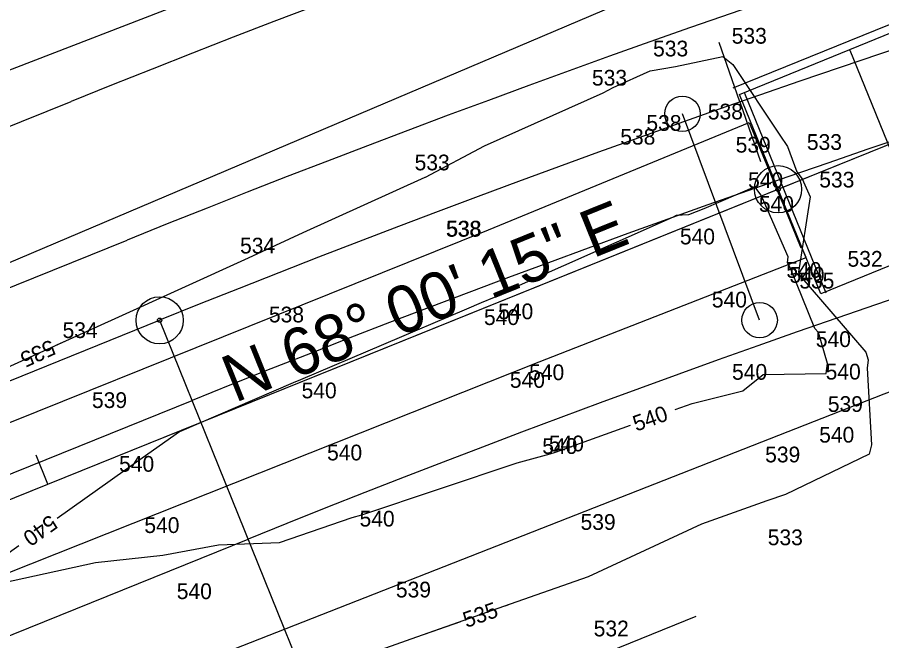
# Model space of a CAD drawing. Extents: x 1787461 to 1970323, y 938412 to 1118748.
# Drawn here: x 1967600.1 to 1967710, y 1117774.7 to 1117853.9 of the extents above; entities that cross this region are included whole.
import ezdxf

# ---------------------------------------------------------------- set-up
doc = ezdxf.new("R2010")
doc.units = 0
for name, color, linetype in [('Default', 7, 'Continuous'), ('HHA ADDITIONAL XSs', 7, 'Continuous'), ('Level 19', 7, 'Continuous'), ('RD_EX_Bridge', 7, 'Continuous'), ('RD_EX_DV_Prop', 7, 'Continuous'), ('RD_EX_Fence_Other', 7, 'Continuous'), ('RD_EX_Misc', 7, 'Continuous'), ('RD_EX_Road', 7, 'Continuous'), ('RD_EX_VEG', 7, 'Continuous'), ('RD_HC_CL', 7, 'Continuous'), ('RD_HC_CL_Rel', 7, 'Continuous'), ('RD_HC_Data', 7, 'Continuous'), ('RD_HC_Data_Rel', 7, 'Continuous'), ('RD_HC_Data_Tic', 7, 'Continuous'), ('RD_HC_Data_Tic_Rel', 7, 'Continuous'), ('RD_PD_Final_TrvlWay', 7, 'Continuous'), ('RD_SMD_Locator', 7, 'Continuous')]:
    doc.layers.add(name, color=color, linetype=linetype)

msp = doc.modelspace()

# ---------------------------------------------------------------- linework, layer by layer
at = {"layer": 'Default'}
for points in [[(1967588.63, 1117804.76), (1967606.77, 1117813), (1967612.54, 1117815.64), (1967629.5, 1117823.35), (1967636.45, 1117826.54), (1967651.98, 1117833.6), (1967652, 1117833.61), (1967659.52, 1117837.57), (1967674.59, 1117844.3), (1967675.89, 1117844.98), (1967680.6, 1117847.09), (1967683.81, 1117847.65), (1967689.8, 1117848.93), (1967691.11, 1117847.9), (1967697.07, 1117838.93), (1967698.06, 1117837.48), (1967699.22, 1117834.26), (1967699.9, 1117833.4), (1967700.92, 1117831.08), (1967699.46, 1117821.5), (1967699.48, 1117821.47), (1967699.63, 1117821.09), (1967708.02, 1117811.34), (1967708.3, 1117810.39), (1967708.17, 1117809.3), (1967708.72, 1117799.55), (1967708.42, 1117798.39), (1967697.77, 1117793.27), (1967695.42, 1117792.44), (1967687.12, 1117789.5), (1967672.71, 1117782.8), (1967662.77, 1117779.31), (1967650.85, 1117775.1), (1967634.97, 1117769.49)], [(1967605.16, 1117812.27), (1967606.77, 1117813), (1967612.54, 1117815.64), (1967629.5, 1117823.35), (1967636.45, 1117826.54), (1967651.98, 1117833.6), (1967652, 1117833.61), (1967659.52, 1117837.57), (1967674.59, 1117844.3), (1967675.89, 1117844.98), (1967680.6, 1117847.09), (1967683.81, 1117847.65), (1967689.8, 1117848.93), (1967691.11, 1117847.9), (1967697.07, 1117838.93), (1967698.06, 1117837.48), (1967699.22, 1117834.26), (1967699.9, 1117833.4), (1967700.92, 1117831.08), (1967699.46, 1117821.5), (1967699.48, 1117821.47), (1967699.63, 1117821.09), (1967708.02, 1117811.34), (1967708.3, 1117810.39), (1967708.17, 1117809.3), (1967708.72, 1117799.55), (1967708.42, 1117798.39), (1967697.77, 1117793.27), (1967695.42, 1117792.44), (1967687.12, 1117789.5), (1967672.71, 1117782.8), (1967662.77, 1117779.31), (1967662.13, 1117779.08)], [(1967605.16, 1117812.27), (1967606.77, 1117813), (1967612.54, 1117815.64), (1967629.5, 1117823.35), (1967636.45, 1117826.54), (1967651.98, 1117833.6), (1967652, 1117833.61), (1967659.52, 1117837.57), (1967674.59, 1117844.3), (1967675.89, 1117844.98), (1967680.6, 1117847.09), (1967683.81, 1117847.65), (1967689.8, 1117848.93), (1967691.11, 1117847.9), (1967697.07, 1117838.93), (1967698.06, 1117837.48), (1967699.22, 1117834.26), (1967699.9, 1117833.4), (1967700.92, 1117831.08), (1967699.46, 1117821.5), (1967699.48, 1117821.47), (1967699.63, 1117821.09), (1967708.02, 1117811.34), (1967708.3, 1117810.39), (1967708.17, 1117809.3), (1967708.72, 1117799.55), (1967708.42, 1117798.39), (1967697.77, 1117793.27), (1967695.42, 1117792.44), (1967687.12, 1117789.5), (1967672.71, 1117782.8), (1967662.77, 1117779.31), (1967662.13, 1117779.08)], [(1967605.16, 1117812.27), (1967606.77, 1117813), (1967612.54, 1117815.64), (1967629.5, 1117823.35), (1967636.45, 1117826.54), (1967651.98, 1117833.6), (1967652, 1117833.61), (1967659.52, 1117837.57), (1967674.59, 1117844.3), (1967675.89, 1117844.98), (1967680.6, 1117847.09), (1967683.81, 1117847.65), (1967689.8, 1117848.93), (1967691.11, 1117847.9), (1967697.07, 1117838.93), (1967698.06, 1117837.48), (1967699.22, 1117834.26), (1967699.9, 1117833.4), (1967700.92, 1117831.08), (1967699.46, 1117821.5), (1967699.48, 1117821.47), (1967699.63, 1117821.09), (1967708.02, 1117811.34), (1967708.3, 1117810.39), (1967708.17, 1117809.3), (1967708.72, 1117799.55), (1967708.42, 1117798.39), (1967697.77, 1117793.27), (1967695.42, 1117792.44), (1967687.12, 1117789.5), (1967672.71, 1117782.8), (1967662.77, 1117779.31), (1967662.13, 1117779.08)], [(1967605.16, 1117812.27), (1967606.77, 1117813), (1967612.54, 1117815.64), (1967629.5, 1117823.35), (1967636.45, 1117826.54), (1967651.98, 1117833.6), (1967652, 1117833.61), (1967659.52, 1117837.57), (1967674.59, 1117844.3), (1967675.89, 1117844.98), (1967680.6, 1117847.09), (1967683.81, 1117847.65), (1967689.8, 1117848.93), (1967691.11, 1117847.9), (1967697.07, 1117838.93), (1967698.06, 1117837.48), (1967699.22, 1117834.26), (1967699.9, 1117833.4), (1967700.92, 1117831.08), (1967699.46, 1117821.5), (1967699.48, 1117821.47), (1967699.63, 1117821.09), (1967708.02, 1117811.34), (1967708.3, 1117810.39), (1967708.17, 1117809.3), (1967708.72, 1117799.55), (1967708.42, 1117798.39), (1967697.77, 1117793.27), (1967695.42, 1117792.44), (1967687.12, 1117789.5), (1967672.71, 1117782.8), (1967662.77, 1117779.31), (1967662.13, 1117779.08)], [(1967605.16, 1117812.27), (1967606.77, 1117813), (1967612.54, 1117815.64), (1967629.5, 1117823.35), (1967636.45, 1117826.54), (1967651.98, 1117833.6), (1967652, 1117833.61), (1967659.52, 1117837.57), (1967674.59, 1117844.3), (1967675.89, 1117844.98), (1967680.6, 1117847.09), (1967683.81, 1117847.65), (1967689.8, 1117848.93), (1967691.11, 1117847.9), (1967697.07, 1117838.93), (1967698.06, 1117837.48), (1967699.22, 1117834.26), (1967699.9, 1117833.4), (1967700.92, 1117831.08), (1967699.46, 1117821.5), (1967699.48, 1117821.47), (1967699.63, 1117821.09), (1967708.02, 1117811.34), (1967708.3, 1117810.39), (1967708.17, 1117809.3), (1967708.72, 1117799.55), (1967708.42, 1117798.39), (1967697.77, 1117793.27), (1967695.42, 1117792.44), (1967687.12, 1117789.5), (1967672.71, 1117782.8), (1967662.77, 1117779.31), (1967662.13, 1117779.08)], [(1967605.16, 1117812.27), (1967606.77, 1117813), (1967612.54, 1117815.64), (1967629.5, 1117823.35), (1967636.45, 1117826.54), (1967651.98, 1117833.6), (1967652, 1117833.61), (1967659.52, 1117837.57), (1967674.59, 1117844.3), (1967675.89, 1117844.98), (1967680.6, 1117847.09), (1967683.81, 1117847.65), (1967689.8, 1117848.93), (1967691.11, 1117847.9), (1967697.07, 1117838.93), (1967698.06, 1117837.48), (1967699.22, 1117834.26), (1967699.9, 1117833.4), (1967700.92, 1117831.08), (1967699.46, 1117821.5), (1967699.48, 1117821.47), (1967699.63, 1117821.09), (1967708.02, 1117811.34), (1967708.3, 1117810.39), (1967708.17, 1117809.3), (1967708.72, 1117799.55), (1967708.42, 1117798.39), (1967697.77, 1117793.27), (1967695.42, 1117792.44), (1967687.12, 1117789.5), (1967672.71, 1117782.8), (1967662.77, 1117779.31), (1967662.13, 1117779.08)], [(1967694.7, 1117831.31), (1967693.87, 1117832.37), (1967687.42, 1117829.58), (1967685.44, 1117828.82), (1967683.88, 1117828.7), (1967683.5, 1117828.5), (1967662.39, 1117819.16), (1967660.76, 1117818.3), (1967659.11, 1117817.6), (1967659.11, 1117817.6), (1967657.23, 1117816.83), (1967636.11, 1117807.81), (1967635.18, 1117807.43), (1967620.73, 1117801.23), (1967613.81, 1117796.33), (1967605.18, 1117790.19)], [(1967694.7, 1117831.31), (1967693.87, 1117832.37), (1967687.42, 1117829.58), (1967685.44, 1117828.82), (1967683.88, 1117828.7), (1967683.5, 1117828.5), (1967662.39, 1117819.16), (1967660.76, 1117818.3), (1967659.11, 1117817.6), (1967659.11, 1117817.6), (1967657.23, 1117816.83), (1967636.11, 1117807.81), (1967635.18, 1117807.43), (1967620.73, 1117801.23), (1967613.81, 1117796.33), (1967605.18, 1117790.19)], [(1967694.7, 1117831.31), (1967693.87, 1117832.37), (1967687.42, 1117829.58), (1967685.44, 1117828.82), (1967683.88, 1117828.7), (1967683.5, 1117828.5), (1967662.39, 1117819.16), (1967660.76, 1117818.3), (1967659.11, 1117817.6), (1967659.11, 1117817.6), (1967657.23, 1117816.83), (1967636.11, 1117807.81), (1967635.18, 1117807.43), (1967620.73, 1117801.23), (1967613.81, 1117796.33), (1967605.18, 1117790.19)], [(1967694.7, 1117831.31), (1967693.87, 1117832.37), (1967687.42, 1117829.58), (1967685.44, 1117828.82), (1967683.88, 1117828.7), (1967683.5, 1117828.5), (1967662.39, 1117819.16), (1967660.76, 1117818.3), (1967659.11, 1117817.6), (1967659.11, 1117817.6), (1967657.23, 1117816.83), (1967636.11, 1117807.81), (1967635.18, 1117807.43), (1967620.73, 1117801.23), (1967613.81, 1117796.33), (1967605.18, 1117790.19)], [(1967694.7, 1117831.31), (1967693.87, 1117832.37), (1967687.42, 1117829.58), (1967685.44, 1117828.82), (1967683.88, 1117828.7), (1967683.5, 1117828.5), (1967662.39, 1117819.16), (1967660.76, 1117818.3), (1967659.11, 1117817.6), (1967659.11, 1117817.6), (1967657.23, 1117816.83), (1967636.11, 1117807.81), (1967635.18, 1117807.43), (1967620.73, 1117801.23), (1967613.81, 1117796.33), (1967605.18, 1117790.19)], [(1967694.7, 1117831.31), (1967693.87, 1117832.37), (1967687.42, 1117829.58), (1967685.44, 1117828.82), (1967683.88, 1117828.7), (1967683.5, 1117828.5), (1967662.39, 1117819.16), (1967660.76, 1117818.3), (1967659.11, 1117817.6), (1967659.11, 1117817.6), (1967657.23, 1117816.83), (1967636.11, 1117807.81), (1967635.18, 1117807.43), (1967620.73, 1117801.23), (1967613.81, 1117796.33), (1967605.18, 1117790.19)], [(1967694.7, 1117831.31), (1967693.87, 1117832.37), (1967687.42, 1117829.58), (1967685.44, 1117828.82), (1967683.88, 1117828.7), (1967683.5, 1117828.5), (1967662.39, 1117819.16), (1967660.76, 1117818.3), (1967659.11, 1117817.6), (1967659.11, 1117817.6), (1967657.23, 1117816.83), (1967636.11, 1117807.81), (1967635.18, 1117807.43), (1967620.73, 1117801.23), (1967613.81, 1117796.33), (1967605.18, 1117790.19)], [(1967683.75, 1117804.06), (1967685.94, 1117804.84), (1967692.35, 1117806.45), (1967694.94, 1117808.51), (1967702.97, 1117808.62), (1967703.12, 1117809.89), (1967701.97, 1117813.86), (1967701.53, 1117814.37), (1967698.39, 1117822.11), (1967698.02, 1117822.7), (1967698.13, 1117823.46), (1967694.7, 1117831.31)], [(1967683.75, 1117804.06), (1967685.94, 1117804.84), (1967692.35, 1117806.45), (1967694.94, 1117808.51), (1967702.97, 1117808.62), (1967703.12, 1117809.89), (1967701.97, 1117813.86), (1967701.53, 1117814.37), (1967698.39, 1117822.11), (1967698.02, 1117822.7), (1967698.13, 1117823.46), (1967694.7, 1117831.31)], [(1967683.75, 1117804.06), (1967685.94, 1117804.84), (1967692.35, 1117806.45), (1967694.94, 1117808.51), (1967702.97, 1117808.62), (1967703.12, 1117809.89), (1967701.97, 1117813.86), (1967701.53, 1117814.37), (1967698.39, 1117822.11), (1967698.02, 1117822.7), (1967698.13, 1117823.46), (1967694.7, 1117831.31)], [(1967683.75, 1117804.06), (1967685.94, 1117804.84), (1967692.35, 1117806.45), (1967694.94, 1117808.51), (1967702.97, 1117808.62), (1967703.12, 1117809.89), (1967701.97, 1117813.86), (1967701.53, 1117814.37), (1967698.39, 1117822.11), (1967698.02, 1117822.7), (1967698.13, 1117823.46), (1967694.7, 1117831.31)], [(1967683.75, 1117804.06), (1967685.94, 1117804.84), (1967692.35, 1117806.45), (1967694.94, 1117808.51), (1967702.97, 1117808.62), (1967703.12, 1117809.89), (1967701.97, 1117813.86), (1967701.53, 1117814.37), (1967698.39, 1117822.11), (1967698.02, 1117822.7), (1967698.13, 1117823.46), (1967694.7, 1117831.31)], [(1967683.75, 1117804.06), (1967685.94, 1117804.84), (1967692.35, 1117806.45), (1967694.94, 1117808.51), (1967702.97, 1117808.62), (1967703.12, 1117809.89), (1967701.97, 1117813.86), (1967701.53, 1117814.37), (1967698.39, 1117822.11), (1967698.02, 1117822.7), (1967698.13, 1117823.46), (1967694.7, 1117831.31)], [(1967683.75, 1117804.06), (1967685.94, 1117804.84), (1967692.35, 1117806.45), (1967694.94, 1117808.51), (1967702.97, 1117808.62), (1967703.12, 1117809.89), (1967701.97, 1117813.86), (1967701.53, 1117814.37), (1967698.39, 1117822.11), (1967698.02, 1117822.7), (1967698.13, 1117823.46), (1967694.7, 1117831.31)], [(1967600.29, 1117786.71), (1967596.07, 1117783.71), (1967592.9, 1117781.45), (1967591.69, 1117780.59), (1967592.73, 1117780.85), (1967593.14, 1117780.91), (1967610.04, 1117784.61), (1967618.63, 1117785.54), (1967625.68, 1117786.84), (1967633.46, 1117787.15), (1967642.7, 1117790.31), (1967643.9, 1117790.65), (1967663.69, 1117797.3), (1967667.86, 1117798.43), (1967668.54, 1117798.65), (1967678.1, 1117802.05)], [(1967600.29, 1117786.71), (1967596.07, 1117783.71), (1967592.9, 1117781.45), (1967591.69, 1117780.59), (1967592.73, 1117780.85), (1967593.14, 1117780.91), (1967610.04, 1117784.61), (1967618.63, 1117785.54), (1967625.68, 1117786.84), (1967633.46, 1117787.15), (1967642.7, 1117790.31), (1967643.9, 1117790.65), (1967663.69, 1117797.3), (1967667.86, 1117798.43), (1967668.54, 1117798.65), (1967678.1, 1117802.05)], [(1967600.29, 1117786.71), (1967596.07, 1117783.71), (1967592.9, 1117781.45), (1967591.69, 1117780.59), (1967592.73, 1117780.85), (1967593.14, 1117780.91), (1967610.04, 1117784.61), (1967618.63, 1117785.54), (1967625.68, 1117786.84), (1967633.46, 1117787.15), (1967642.7, 1117790.31), (1967643.9, 1117790.65), (1967663.69, 1117797.3), (1967667.86, 1117798.43), (1967668.54, 1117798.65), (1967678.1, 1117802.05)], [(1967600.29, 1117786.71), (1967596.07, 1117783.71), (1967592.9, 1117781.45), (1967591.69, 1117780.59), (1967592.73, 1117780.85), (1967593.14, 1117780.91), (1967610.04, 1117784.61), (1967618.63, 1117785.54), (1967625.68, 1117786.84), (1967633.46, 1117787.15), (1967642.7, 1117790.31), (1967643.9, 1117790.65), (1967663.69, 1117797.3), (1967667.86, 1117798.43), (1967668.54, 1117798.65), (1967678.1, 1117802.05)], [(1967600.29, 1117786.71), (1967596.07, 1117783.71), (1967592.9, 1117781.45), (1967591.69, 1117780.59), (1967592.73, 1117780.85), (1967593.14, 1117780.91), (1967610.04, 1117784.61), (1967618.63, 1117785.54), (1967625.68, 1117786.84), (1967633.46, 1117787.15), (1967642.7, 1117790.31), (1967643.9, 1117790.65), (1967663.69, 1117797.3), (1967667.86, 1117798.43), (1967668.54, 1117798.65), (1967678.1, 1117802.05)], [(1967600.29, 1117786.71), (1967596.07, 1117783.71), (1967592.9, 1117781.45), (1967591.69, 1117780.59), (1967592.73, 1117780.85), (1967593.14, 1117780.91), (1967610.04, 1117784.61), (1967618.63, 1117785.54), (1967625.68, 1117786.84), (1967633.46, 1117787.15), (1967642.7, 1117790.31), (1967643.9, 1117790.65), (1967663.69, 1117797.3), (1967667.86, 1117798.43), (1967668.54, 1117798.65), (1967678.1, 1117802.05)], [(1967600.29, 1117786.71), (1967596.07, 1117783.71), (1967592.9, 1117781.45), (1967591.69, 1117780.59), (1967592.73, 1117780.85), (1967593.14, 1117780.91), (1967610.04, 1117784.61), (1967618.63, 1117785.54), (1967625.68, 1117786.84), (1967633.46, 1117787.15), (1967642.7, 1117790.31), (1967643.9, 1117790.65), (1967663.69, 1117797.3), (1967667.86, 1117798.43), (1967668.54, 1117798.65), (1967678.1, 1117802.05)], [(1967656.47, 1117777.08), (1967650.85, 1117775.1), (1967634.97, 1117769.49), (1967627.29, 1117766.79), (1967610.06, 1117760.7), (1967603.74, 1117758.49), (1967584.74, 1117751.76), (1967580.2, 1117750.17), (1967577.14, 1117748.82), (1967576.43, 1117748.53), (1967554.96, 1117739.06), (1967553.54, 1117738.47), (1967543.93, 1117734.19), (1967539.4, 1117728.42), (1967538.83, 1117723.7), (1967524.23, 1117678.01), (1967542.42, 1117671.22)], [(1967656.47, 1117777.08), (1967650.85, 1117775.1), (1967634.97, 1117769.49), (1967627.29, 1117766.79), (1967610.06, 1117760.7), (1967603.74, 1117758.49), (1967584.74, 1117751.76), (1967580.2, 1117750.17), (1967577.14, 1117748.82), (1967576.43, 1117748.53), (1967554.96, 1117739.06), (1967553.54, 1117738.47), (1967543.93, 1117734.19), (1967539.4, 1117728.42), (1967538.83, 1117723.7), (1967524.23, 1117678.01), (1967542.42, 1117671.22)], [(1967656.47, 1117777.08), (1967650.85, 1117775.1), (1967634.97, 1117769.49), (1967627.29, 1117766.79), (1967610.06, 1117760.7), (1967603.74, 1117758.49), (1967584.74, 1117751.76), (1967580.2, 1117750.17), (1967577.14, 1117748.82), (1967576.43, 1117748.53), (1967554.96, 1117739.06), (1967553.54, 1117738.47), (1967543.93, 1117734.19), (1967539.4, 1117728.42), (1967538.83, 1117723.7), (1967524.23, 1117678.01), (1967542.42, 1117671.22)], [(1967656.47, 1117777.08), (1967650.85, 1117775.1), (1967634.97, 1117769.49), (1967627.29, 1117766.79), (1967610.06, 1117760.7), (1967603.74, 1117758.49), (1967584.74, 1117751.76), (1967580.2, 1117750.17), (1967577.14, 1117748.82), (1967576.43, 1117748.53), (1967554.96, 1117739.06), (1967553.54, 1117738.47), (1967543.93, 1117734.19), (1967539.4, 1117728.42), (1967538.83, 1117723.7), (1967524.23, 1117678.01), (1967542.42, 1117671.22)], [(1967656.47, 1117777.08), (1967650.85, 1117775.1), (1967634.97, 1117769.49), (1967627.29, 1117766.79), (1967610.06, 1117760.7), (1967603.74, 1117758.49), (1967584.74, 1117751.76), (1967580.2, 1117750.17), (1967577.14, 1117748.82), (1967576.43, 1117748.53), (1967554.96, 1117739.06), (1967553.54, 1117738.47), (1967543.93, 1117734.19), (1967539.4, 1117728.42), (1967538.83, 1117723.7), (1967524.23, 1117678.01), (1967542.42, 1117671.22)], [(1967656.47, 1117777.08), (1967650.85, 1117775.1), (1967634.97, 1117769.49), (1967627.29, 1117766.79), (1967610.06, 1117760.7), (1967603.74, 1117758.49), (1967584.74, 1117751.76), (1967580.2, 1117750.17), (1967577.14, 1117748.82), (1967576.43, 1117748.53), (1967554.96, 1117739.06), (1967553.54, 1117738.47), (1967543.93, 1117734.19), (1967539.4, 1117728.42), (1967538.83, 1117723.7), (1967524.23, 1117678.01), (1967542.42, 1117671.22)]]:
    msp.add_lwpolyline(points, dxfattribs=at)
at = {"layer": 'HHA ADDITIONAL XSs'}
for p, q in [((1967355.97, 1117741.82), (1967606.98, 1117843.22)), ((1967378.44, 1117686.19), (1967629.45, 1117787.58))]:
    msp.add_line(p, q, dxfattribs=at)
msp.add_lwpolyline([(1969266.55, 1117963.61), (1967907.56, 1117966.55), (1967403.98, 1117771.66), (1967075.57, 1117641.84)], dxfattribs=at)
for radius in [1667.02, 1607.02]:
    msp.add_arc((1968231.34, 1116297.54), radius, 87.72663, 111.99584, dxfattribs=at)
at = {"layer": 'Level 19'}
msp.add_line((1967694.5, 1117815.42), (1967684.68, 1117841.64), dxfattribs=at)
for centre in [(1967684.68, 1117841.64), (1967694.5, 1117815.42)]:
    msp.add_circle(centre, 2.25, dxfattribs=at)
at = {"layer": 'RD_EX_Bridge'}
msp.add_lwpolyline([(1967691.93, 1117844.09), (1967872.42, 1117917.74), (1967882.76, 1117892.41), (1967702.27, 1117818.76), (1967691.93, 1117844.09)], dxfattribs=at)
at = {"layer": 'RD_EX_DV_Prop'}
for p, q in [((1967696.84, 1117832.06), (1967823.97, 1117883.41)), ((1966769.51, 1117457.48), (1967696.84, 1117832.06))]:
    msp.add_line(p, q, dxfattribs=at)
at = {"layer": 'RD_EX_Fence_Other'}
msp.add_lwpolyline([(1967531.32, 1117716.68), (1967581.91, 1117735.39), (1967686.43, 1117777.78)], dxfattribs=at)
at = {"layer": 'RD_EX_Misc'}
for p, q in [((1967691.12, 1117844.93), (1967873.24, 1117918.94)), ((1967705.98, 1117849.73), (1967716.27, 1117824.34)), ((1967692.59, 1117844.26), (1967702.91, 1117818.87))]:
    msp.add_line(p, q, dxfattribs=at)
at = {"layer": 'RD_EX_Road'}
for points in [[(1966768.28, 1117466.83), (1966868.93, 1117506.7), (1966969.96, 1117548.31), (1967069.86, 1117589.6), (1967171.37, 1117630.89), (1967269.56, 1117671.02), (1967319.89, 1117691.93), (1967370.29, 1117712.23), (1967469.03, 1117750.91), (1967565.44, 1117788.86), (1967660.02, 1117826.88), (1967693.17, 1117840.55), (1967696.66, 1117832.16)], [(1967338.81, 1117679.22), (1967378.03, 1117695.56), (1967474.86, 1117733.75), (1967572.69, 1117772.86), (1967666.47, 1117810.1), (1967700.41, 1117823.36), (1967696.66, 1117832.16)]]:
    msp.add_lwpolyline(points, dxfattribs=at)
at = {"layer": 'RD_EX_VEG'}
for points in [[(1967420.8, 1117819.08), (1967452.15, 1117758.28), (1967558.57, 1117805.53), (1967843.24, 1117926.43), (1967916.63, 1117956.61), (1968008.44, 1117968.2), (1968060.25, 1117967.44), (1968104.58, 1117972.69), (1968157.63, 1117966.15), (1968211.15, 1117963.44), (1968421.93, 1117955.99), (1968535.19, 1117951.62)], [(1967302.31, 1117610.37), (1967337.76, 1117649.58), (1967352.05, 1117663.92), (1967393.53, 1117676.59), (1967483.38, 1117717.02), (1967710.35, 1117806.03), (1967888.86, 1117873.57), (1967928.06, 1117882.04), (1967957.92, 1117887.35), (1967975.7, 1117893.86), (1968013.09, 1117903.71), (1968102.91, 1117899.22), (1968154.08, 1117904.84), (1968208.62, 1117905.24), (1968319.32, 1117902.87), (1968421.81, 1117901.58), (1968527.92, 1117886.31)]]:
    msp.add_lwpolyline(points, dxfattribs=at)
at = {"layer": 'RD_HC_CL'}
msp.add_line((1966769.51, 1117457.48), (1967848.24, 1117893.22), dxfattribs=at)
at = {"layer": 'RD_HC_CL_Rel'}
msp.add_line((1967367.21, 1117714.01), (1967618.21, 1117815.4), dxfattribs=at)
msp.add_arc((1968231.34, 1116297.54), 1637.02, 87.72663, 111.99584, dxfattribs=at)
at = {"layer": 'RD_HC_Data'}
for radius in [3, 0.282]:
    msp.add_circle((1967696.84, 1117832.06), radius, dxfattribs=at)
at = {"layer": 'RD_HC_Data_Rel'}
msp.add_line((1967618.21, 1117815.4), (1967674.03, 1117677.23), dxfattribs=at)
for radius in [3, 0.282]:
    msp.add_circle((1967618.21, 1117815.4), radius, dxfattribs=at)
at = {"layer": 'RD_HC_Data_Tic'}
for p, q in [((1967696.72, 1117832.01), (1967693.73, 1117839.43)), ((1967696.72, 1117832.01), (1967699.72, 1117824.6)), ((1967604, 1117794.56), (1967602.5, 1117798.27))]:
    msp.add_line(p, q, dxfattribs=at)
at = {"layer": 'RD_HC_Data_Tic_Rel'}
for q in [(1967689.34, 1117850.7), (1967694.61, 1117835.6)]:
    msp.add_line((1967691.97, 1117843.15), q, dxfattribs=at)
at = {"layer": 'RD_PD_Final_TrvlWay'}
for p, q in [((1967363.09, 1117724.21), (1967614.09, 1117825.6)), ((1967371.33, 1117703.81), (1967622.33, 1117805.2))]:
    msp.add_line(p, q, dxfattribs=at)
for radius in [1648.02, 1626.02]:
    msp.add_arc((1968231.34, 1116297.54), radius, 87.72663, 111.99584, dxfattribs=at)
at = {"layer": 'RD_SMD_Locator'}
msp.add_circle((1967696.84, 1117832.06), 0.001, dxfattribs=at)

# ---------------------------------------------------------------- texts
at = {"layer": 'Default'}
for s, p in [('533', (1967690.95, 1117850.56)), ('533', (1967680.95, 1117848.94)), ('533', (1967673.18, 1117845.23)), ('538', (1967687.91, 1117840.93)), ('538', (1967680.1, 1117839.48)), ('538', (1967676.78, 1117837.73)), ('539', (1967691.45, 1117836.71)), ('533', (1967700.5, 1117837.06)), ('533', (1967650.63, 1117834.46)), ('540', (1967693.03, 1117832.22)), ('533', (1967702.08, 1117832.28)), ('540', (1967694.4, 1117829.19)), ('538', (1967654.61, 1117826.02)), ('538', (1967654.68, 1117826.05)), ('540', (1967684.36, 1117825.05)), ('534', (1967628.44, 1117823.89)), ('532', (1967705.67, 1117822.21)), ('540', (1967697.89, 1117820.8)), ('540', (1967698.29, 1117820.17)), ('535', (1967699.54, 1117819.44)), ('540', (1967688.42, 1117817.03)), ('540', (1967661.25, 1117815.53)), ('538', (1967632.11, 1117815.13)), ('540', (1967659.45, 1117814.8)), ('534', (1967605.87, 1117813.14)), ('540', (1967701.64, 1117812)), ('540', (1967665.19, 1117807.79)), ('540', (1967690.99, 1117807.84)), ('540', (1967702.89, 1117807.87)), ('540', (1967662.74, 1117806.82)), ('540', (1967636.26, 1117805.48)), ('539', (1967609.61, 1117804.25)), ('539', (1967703.17, 1117803.75)), ('540', (1967702.07, 1117799.85)), ('540', (1967667.7, 1117798.74)), ('540', (1967639.5, 1117797.59)), ('540', (1967666.86, 1117798.41)), ('539', (1967695.2, 1117797.34)), ('540', (1967613.06, 1117796.15)), ('540', (1967643.63, 1117789.18)), ('540', (1967616.27, 1117788.36)), ('539', (1967671.73, 1117788.76)), ('533', (1967695.53, 1117786.81)), ('539', (1967648.25, 1117780.17)), ('540', (1967620.39, 1117779.96)), ('532', (1967673.4, 1117775.22))]:
    msp.add_text(s, height=2, dxfattribs=at).set_placement(p)
for s, rotation, p in [('535', 204.4249, (1967604.36, 1117813)), ('535', 204.4249, (1967604.36, 1117813)), ('535', 204.4249, (1967604.36, 1117813)), ('535', 204.4249, (1967604.36, 1117813)), ('535', 204.4249, (1967604.36, 1117813)), ('535', 204.4249, (1967604.36, 1117813)), ('540', 19.5727, (1967678.81, 1117801.24)), ('540', 19.5727, (1967678.81, 1117801.24)), ('540', 19.5727, (1967678.81, 1117801.24)), ('540', 19.5727, (1967678.81, 1117801.24)), ('540', 19.5727, (1967678.81, 1117801.24)), ('540', 19.5727, (1967678.81, 1117801.24)), ('540', 19.5727, (1967678.81, 1117801.24)), ('540', 215.4252, (1967604.28, 1117790.77)), ('540', 215.4252, (1967604.28, 1117790.77)), ('540', 215.4252, (1967604.28, 1117790.77)), ('540', 215.4252, (1967604.28, 1117790.77)), ('540', 215.4252, (1967604.28, 1117790.77)), ('540', 215.4252, (1967604.28, 1117790.77)), ('540', 215.4252, (1967604.28, 1117790.77)), ('535', 19.457, (1967657.21, 1117776.28)), ('535', 19.457, (1967657.21, 1117776.28)), ('535', 19.457, (1967657.21, 1117776.28)), ('535', 19.457, (1967657.21, 1117776.28)), ('535', 19.457, (1967657.21, 1117776.28)), ('535', 19.457, (1967657.21, 1117776.28))]:
    msp.add_text(s, height=2, rotation=rotation, dxfattribs=at).set_placement(p)
at = {"layer": 'RD_HC_Data'}
msp.add_text('N 68%%d 00\' 15" E', height=6, rotation=21.9958, dxfattribs=at).set_placement((1967627.77, 1117804.87))

doc.saveas('drawing.dxf')
